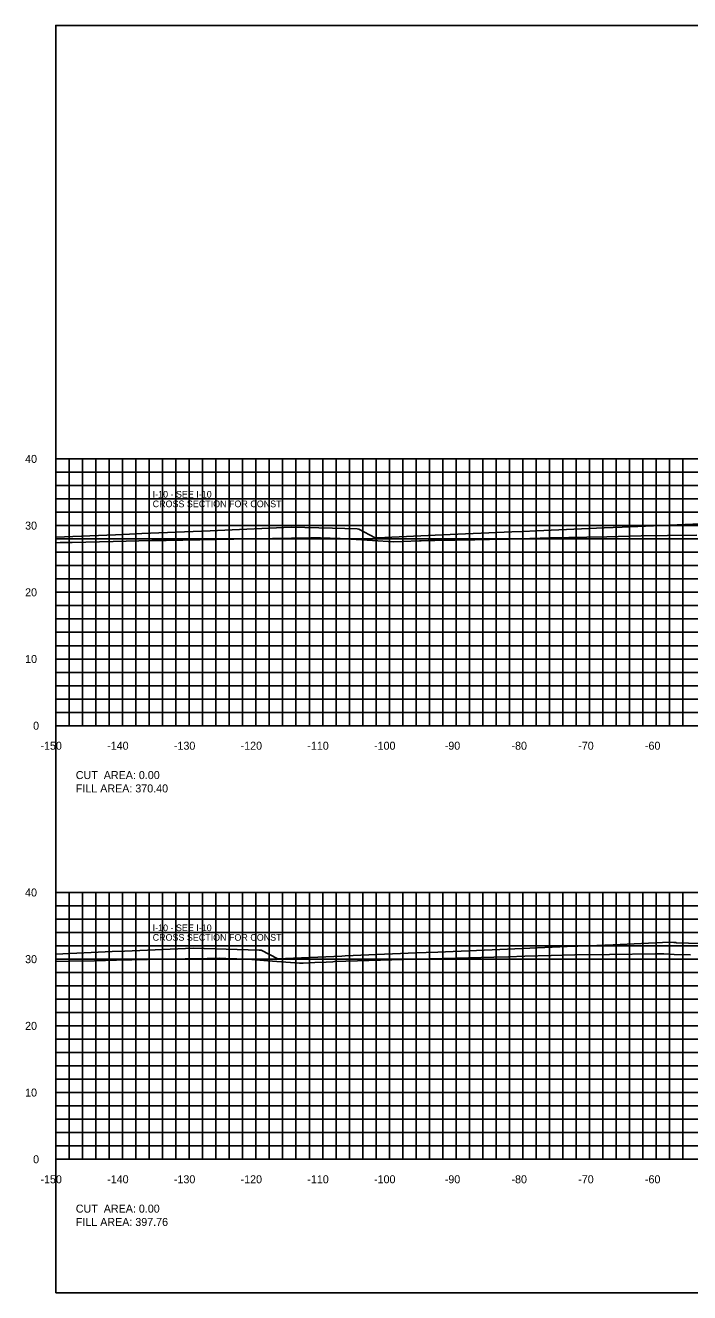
# Model space of a CAD drawing. Extents: x 1797652 to 1804145, y 245981 to 250269.
# Drawn here: x 1803156.4 to 1803256, y 250079.4 to 250269.4 of the extents above; entities that cross this region are included whole.
import ezdxf

# ---------------------------------------------------------------- set-up
doc = ezdxf.new("R2010")
doc.units = 0
for name, color, linetype in [('10', 7, 'Continuous'), ('3', 7, 'Continuous'), ('31', 7, 'Continuous'), ('60', 7, 'Continuous'), ('ANNO-TXT', 7, 'Continuous'), ('CL-CNST', 7, 'Continuous'), ('Level 62', 7, 'Continuous'), ('M-ROADS', 7, 'Continuous')]:
    doc.layers.add(name, color=color, linetype=linetype)

msp = doc.modelspace()

# ---------------------------------------------------------------- linework, layer by layer
msp.add_lwpolyline([(1803161, 250079.43), (1803461, 250079.43), (1803461, 250269.43), (1803161, 250269.43)], close=True)
at = {"layer": '60'}
for p, q in [((1803160.94, 250204.43), (1803161, 250204.43)), ((1803161, 250164.43), (1803161, 250204.43)), ((1803160.94, 250194.43), (1803161, 250194.43)), ((1803160.94, 250184.43), (1803161, 250184.43)), ((1803160.94, 250174.43), (1803161, 250174.43)), ((1803160.94, 250164.43), (1803161, 250164.43)), ((1803161, 250164.43), (1803461, 250164.43)), ((1803161, 250164.37), (1803161, 250164.43)), ((1803171, 250164.37), (1803171, 250164.43)), ((1803181, 250164.37), (1803181, 250164.43)), ((1803191, 250164.37), (1803191, 250164.43)), ((1803201, 250164.37), (1803201, 250164.43)), ((1803211, 250164.37), (1803211, 250164.43)), ((1803221, 250164.37), (1803221, 250164.43)), ((1803231, 250164.37), (1803231, 250164.43)), ((1803241, 250164.37), (1803241, 250164.43)), ((1803251, 250164.37), (1803251, 250164.43)), ((1803160.94, 250139.43), (1803161, 250139.43)), ((1803161, 250099.43), (1803161, 250139.43)), ((1803160.94, 250129.43), (1803161, 250129.43)), ((1803160.94, 250119.43), (1803161, 250119.43)), ((1803160.94, 250109.43), (1803161, 250109.43)), ((1803160.94, 250099.43), (1803161, 250099.43)), ((1803161, 250099.43), (1803461, 250099.43)), ((1803161, 250099.37), (1803161, 250099.43)), ((1803171, 250099.37), (1803171, 250099.43)), ((1803181, 250099.37), (1803181, 250099.43)), ((1803191, 250099.37), (1803191, 250099.43)), ((1803201, 250099.37), (1803201, 250099.43)), ((1803211, 250099.37), (1803211, 250099.43)), ((1803221, 250099.37), (1803221, 250099.43)), ((1803231, 250099.37), (1803231, 250099.43)), ((1803241, 250099.37), (1803241, 250099.43)), ((1803251, 250099.37), (1803251, 250099.43))]:
    msp.add_line(p, q, dxfattribs=at)
at = {"layer": 'CL-CNST'}
for points in [[(1803161, 250192.68), (1803169.95, 250193.07), (1803172.05, 250193.15), (1803173.89, 250193.23), (1803184.16, 250193.67), (1803185.26, 250193.72), (1803196.27, 250194.19), (1803202.46, 250194.03), (1803206.16, 250193.93), (1803206.36, 250193.92), (1803206.41, 250193.9), (1803208.88, 250192.61), (1803209.24, 250192.62), (1803218.97, 250193.04), (1803229.36, 250193.49), (1803231.07, 250193.56), (1803233, 250193.64), (1803243.17, 250194.08), (1803245.9, 250194.2), (1803255.27, 250194.6), (1803263.52, 250194.95)], [(1803161, 250130.2), (1803169.44, 250130.56), (1803171.3, 250130.64), (1803181.6, 250131.07), (1803191.47, 250130.8), (1803191.73, 250130.8), (1803191.79, 250130.77), (1803194.26, 250129.48), (1803195.44, 250129.53), (1803203.85, 250129.88), (1803204.38, 250129.91), (1803215.03, 250130.36), (1803216.53, 250130.42), (1803218.26, 250130.49), (1803228.68, 250130.93), (1803237.62, 250131.31), (1803240.82, 250131.45), (1803244.53, 250131.6), (1803252.97, 250131.96), (1803253.61, 250131.93), (1803253.98, 250131.92), (1803254, 250131.9), (1803254.03, 250131.86), (1803259.49, 250131.72)]]:
    msp.add_lwpolyline(points, dxfattribs=at)
at = {"layer": 'Level 62'}
for p, q in [((1803161, 250204.43), (1803461, 250204.43)), ((1803161, 250164.43), (1803161, 250204.43)), ((1803163, 250164.43), (1803163, 250204.43)), ((1803165, 250164.43), (1803165, 250204.43)), ((1803167, 250164.43), (1803167, 250204.43)), ((1803169, 250164.43), (1803169, 250204.43)), ((1803171, 250164.43), (1803171, 250204.43)), ((1803173, 250164.43), (1803173, 250204.43)), ((1803175, 250164.43), (1803175, 250204.43)), ((1803177, 250164.43), (1803177, 250204.43)), ((1803179, 250164.43), (1803179, 250204.43)), ((1803181, 250164.43), (1803181, 250204.43)), ((1803183, 250164.43), (1803183, 250204.43)), ((1803185, 250164.43), (1803185, 250204.43)), ((1803187, 250164.43), (1803187, 250204.43)), ((1803189, 250164.43), (1803189, 250204.43)), ((1803191, 250164.43), (1803191, 250204.43)), ((1803193, 250164.43), (1803193, 250204.43)), ((1803195, 250164.43), (1803195, 250204.43)), ((1803197, 250164.43), (1803197, 250204.43)), ((1803199, 250164.43), (1803199, 250204.43)), ((1803201, 250164.43), (1803201, 250204.43)), ((1803203, 250164.43), (1803203, 250204.43)), ((1803205, 250164.43), (1803205, 250204.43)), ((1803207, 250164.43), (1803207, 250204.43)), ((1803209, 250164.43), (1803209, 250204.43)), ((1803211, 250164.43), (1803211, 250204.43)), ((1803213, 250164.43), (1803213, 250204.43)), ((1803215, 250164.43), (1803215, 250204.43)), ((1803217, 250164.43), (1803217, 250204.43)), ((1803219, 250164.43), (1803219, 250204.43)), ((1803221, 250164.43), (1803221, 250204.43)), ((1803223, 250164.43), (1803223, 250204.43)), ((1803225, 250164.43), (1803225, 250204.43)), ((1803227, 250164.43), (1803227, 250204.43)), ((1803229, 250164.43), (1803229, 250204.43)), ((1803231, 250164.43), (1803231, 250204.43)), ((1803233, 250164.43), (1803233, 250204.43)), ((1803235, 250164.43), (1803235, 250204.43)), ((1803237, 250164.43), (1803237, 250204.43)), ((1803239, 250164.43), (1803239, 250204.43)), ((1803241, 250164.43), (1803241, 250204.43)), ((1803243, 250164.43), (1803243, 250204.43)), ((1803245, 250164.43), (1803245, 250204.43)), ((1803247, 250164.43), (1803247, 250204.43)), ((1803249, 250164.43), (1803249, 250204.43)), ((1803251, 250164.43), (1803251, 250204.43)), ((1803253, 250164.43), (1803253, 250204.43)), ((1803255, 250164.43), (1803255, 250204.43)), ((1803161, 250202.43), (1803461, 250202.43)), ((1803161, 250200.43), (1803461, 250200.43)), ((1803161, 250198.43), (1803461, 250198.43)), ((1803161, 250196.43), (1803461, 250196.43)), ((1803161, 250194.43), (1803461, 250194.43)), ((1803161, 250192.43), (1803461, 250192.43)), ((1803161, 250190.43), (1803461, 250190.43)), ((1803161, 250188.43), (1803461, 250188.43)), ((1803161, 250186.43), (1803461, 250186.43)), ((1803161, 250184.43), (1803461, 250184.43)), ((1803161, 250182.43), (1803461, 250182.43)), ((1803161, 250180.43), (1803461, 250180.43)), ((1803161, 250178.43), (1803461, 250178.43)), ((1803161, 250176.43), (1803461, 250176.43)), ((1803161, 250174.43), (1803461, 250174.43)), ((1803161, 250172.43), (1803461, 250172.43)), ((1803161, 250170.43), (1803461, 250170.43)), ((1803161, 250168.43), (1803461, 250168.43)), ((1803161, 250166.43), (1803461, 250166.43)), ((1803161, 250164.43), (1803461, 250164.43)), ((1803161, 250139.43), (1803461, 250139.43)), ((1803161, 250099.43), (1803161, 250139.43)), ((1803163, 250099.43), (1803163, 250139.43)), ((1803165, 250099.43), (1803165, 250139.43)), ((1803167, 250099.43), (1803167, 250139.43)), ((1803169, 250099.43), (1803169, 250139.43)), ((1803171, 250099.43), (1803171, 250139.43)), ((1803173, 250099.43), (1803173, 250139.43)), ((1803175, 250099.43), (1803175, 250139.43)), ((1803177, 250099.43), (1803177, 250139.43)), ((1803179, 250099.43), (1803179, 250139.43)), ((1803181, 250099.43), (1803181, 250139.43)), ((1803183, 250099.43), (1803183, 250139.43)), ((1803185, 250099.43), (1803185, 250139.43)), ((1803187, 250099.43), (1803187, 250139.43)), ((1803189, 250099.43), (1803189, 250139.43)), ((1803191, 250099.43), (1803191, 250139.43)), ((1803193, 250099.43), (1803193, 250139.43)), ((1803195, 250099.43), (1803195, 250139.43)), ((1803197, 250099.43), (1803197, 250139.43)), ((1803199, 250099.43), (1803199, 250139.43)), ((1803201, 250099.43), (1803201, 250139.43)), ((1803203, 250099.43), (1803203, 250139.43)), ((1803205, 250099.43), (1803205, 250139.43)), ((1803207, 250099.43), (1803207, 250139.43)), ((1803209, 250099.43), (1803209, 250139.43)), ((1803211, 250099.43), (1803211, 250139.43)), ((1803213, 250099.43), (1803213, 250139.43)), ((1803215, 250099.43), (1803215, 250139.43)), ((1803217, 250099.43), (1803217, 250139.43)), ((1803219, 250099.43), (1803219, 250139.43)), ((1803221, 250099.43), (1803221, 250139.43)), ((1803223, 250099.43), (1803223, 250139.43)), ((1803225, 250099.43), (1803225, 250139.43)), ((1803227, 250099.43), (1803227, 250139.43)), ((1803229, 250099.43), (1803229, 250139.43)), ((1803231, 250099.43), (1803231, 250139.43)), ((1803233, 250099.43), (1803233, 250139.43)), ((1803235, 250099.43), (1803235, 250139.43)), ((1803237, 250099.43), (1803237, 250139.43)), ((1803239, 250099.43), (1803239, 250139.43)), ((1803241, 250099.43), (1803241, 250139.43)), ((1803243, 250099.43), (1803243, 250139.43)), ((1803245, 250099.43), (1803245, 250139.43)), ((1803247, 250099.43), (1803247, 250139.43)), ((1803249, 250099.43), (1803249, 250139.43)), ((1803251, 250099.43), (1803251, 250139.43)), ((1803253, 250099.43), (1803253, 250139.43)), ((1803255, 250099.43), (1803255, 250139.43)), ((1803161, 250137.43), (1803461, 250137.43)), ((1803161, 250135.43), (1803461, 250135.43)), ((1803161, 250133.43), (1803461, 250133.43)), ((1803161, 250131.43), (1803461, 250131.43)), ((1803161, 250129.43), (1803461, 250129.43)), ((1803161, 250127.43), (1803461, 250127.43)), ((1803161, 250125.43), (1803461, 250125.43)), ((1803161, 250123.43), (1803461, 250123.43)), ((1803161, 250121.43), (1803461, 250121.43)), ((1803161, 250119.43), (1803461, 250119.43)), ((1803161, 250117.43), (1803461, 250117.43)), ((1803161, 250115.43), (1803461, 250115.43)), ((1803161, 250113.43), (1803461, 250113.43)), ((1803161, 250111.43), (1803461, 250111.43)), ((1803161, 250109.43), (1803461, 250109.43)), ((1803161, 250107.43), (1803461, 250107.43)), ((1803161, 250105.43), (1803461, 250105.43)), ((1803161, 250103.43), (1803461, 250103.43)), ((1803161, 250101.43), (1803461, 250101.43)), ((1803161, 250099.43), (1803461, 250099.43))]:
    msp.add_line(p, q, dxfattribs=at)
at = {"layer": 'M-ROADS'}
for points in [[(1803161, 250191.86), (1803161.67, 250191.88), (1803163.44, 250191.92), (1803169.62, 250192.07), (1803175.38, 250192.18), (1803177.56, 250192.22), (1803187.62, 250192.41), (1803187.7, 250192.41), (1803199.24, 250192.59), (1803200.48, 250192.58), (1803200.5, 250192.58), (1803200.65, 250192.58), (1803203.63, 250192.49), (1803204.42, 250192.46), (1803208.48, 250192.19), (1803211.59, 250191.99), (1803212.94, 250192.05), (1803215.53, 250192.17), (1803215.74, 250192.17), (1803216.79, 250192.2), (1803217.81, 250192.22), (1803223.8, 250192.32), (1803228.21, 250192.41), (1803228.96, 250192.42), (1803235.17, 250192.58), (1803240.58, 250192.7), (1803243.61, 250192.76), (1803248.76, 250192.88), (1803252.7, 250192.96), (1803257.09, 250192.98)], [(1803161, 250129.06), (1803163.07, 250129.11), (1803166.78, 250129.2), (1803170.1, 250129.29), (1803172.41, 250129.34), (1803177.08, 250129.41), (1803183.71, 250129.54), (1803184.04, 250129.55), (1803184.29, 250129.55), (1803184.34, 250129.55), (1803185.56, 250129.56), (1803186.46, 250129.53), (1803189.77, 250129.43), (1803192.8, 250129.2), (1803197.54, 250128.82), (1803198.08, 250128.84), (1803199.82, 250128.92), (1803201.5, 250129), (1803202.5, 250129.05), (1803202.76, 250129.06), (1803211.39, 250129.31), (1803214.96, 250129.41), (1803220.94, 250129.56), (1803226.66, 250129.72), (1803228.85, 250129.79), (1803231.3, 250129.86), (1803235.25, 250129.97), (1803238.81, 250130.08), (1803243.98, 250130.15), (1803250.85, 250130.25), (1803251.32, 250130.24), (1803252.12, 250130.21), (1803253.7, 250130.15), (1803256.11, 250130.06)]]:
    msp.add_lwpolyline(points, dxfattribs=at)

# ---------------------------------------------------------------- texts
at = {"layer": '10'}
for s, p in [('-150', (1803158.7, 250160.83)), ('-140', (1803168.7, 250160.83)), ('-130', (1803178.7, 250160.83)), ('-120', (1803188.7, 250160.83)), ('-110', (1803198.7, 250160.83)), ('-100', (1803208.7, 250160.83)), ('-90', (1803219.3, 250160.83)), ('-80', (1803229.3, 250160.83)), ('-70', (1803239.3, 250160.83)), ('-60', (1803249.3, 250160.83)), ('-150', (1803158.7, 250095.83)), ('-140', (1803168.7, 250095.83)), ('-130', (1803178.7, 250095.83)), ('-120', (1803188.7, 250095.83)), ('-110', (1803198.7, 250095.83)), ('-100', (1803208.7, 250095.83)), ('-90', (1803219.3, 250095.83)), ('-80', (1803229.3, 250095.83)), ('-70', (1803239.3, 250095.83)), ('-60', (1803249.3, 250095.83))]:
    msp.add_text(s, height=1.2, dxfattribs=at).set_placement(p)
at = {"layer": '3'}
for s, p in [('I-10 - SEE I-10', (1803175.52, 250198.63)), ('CROSS SECTION FOR CONST ', (1803175.52, 250197.19)), ('CROSS SECTION FOR CONST ', (1803175.52, 250132.19)), ('I-10 - SEE I-10', (1803175.52, 250133.63))]:
    msp.add_text(s, height=1, dxfattribs=at).set_placement(p)
at = {"layer": '31'}
for s, p in [('40', (1803156.4, 250203.83)), ('30', (1803156.4, 250193.83)), ('20', (1803156.4, 250183.83)), ('10', (1803156.4, 250173.83)), ('0', (1803157.6, 250163.83)), ('40', (1803156.4, 250138.83)), ('30', (1803156.4, 250128.83)), ('20', (1803156.4, 250118.83)), ('10', (1803156.4, 250108.83)), ('0', (1803157.6, 250098.83))]:
    msp.add_text(s, height=1.2, dxfattribs=at).set_placement(p)
at = {"layer": '60'}
for p in [(1803161, 250164.43), (1803161, 250099.43)]:
    msp.add_text('-', height=0.0001, dxfattribs=at).set_placement(p)
at = {"layer": 'ANNO-TXT'}
for s, p in [('CUT  AREA: 0.00', (1803164, 250156.43)), ('FILL AREA: 370.40', (1803164, 250154.43)), ('CUT  AREA: 0.00', (1803164, 250091.43)), ('FILL AREA: 397.76', (1803164, 250089.43))]:
    msp.add_text(s, height=1.2, dxfattribs=at).set_placement(p)

doc.saveas('drawing.dxf')
